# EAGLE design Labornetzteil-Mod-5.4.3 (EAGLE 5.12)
OC_FARNELL: unknown
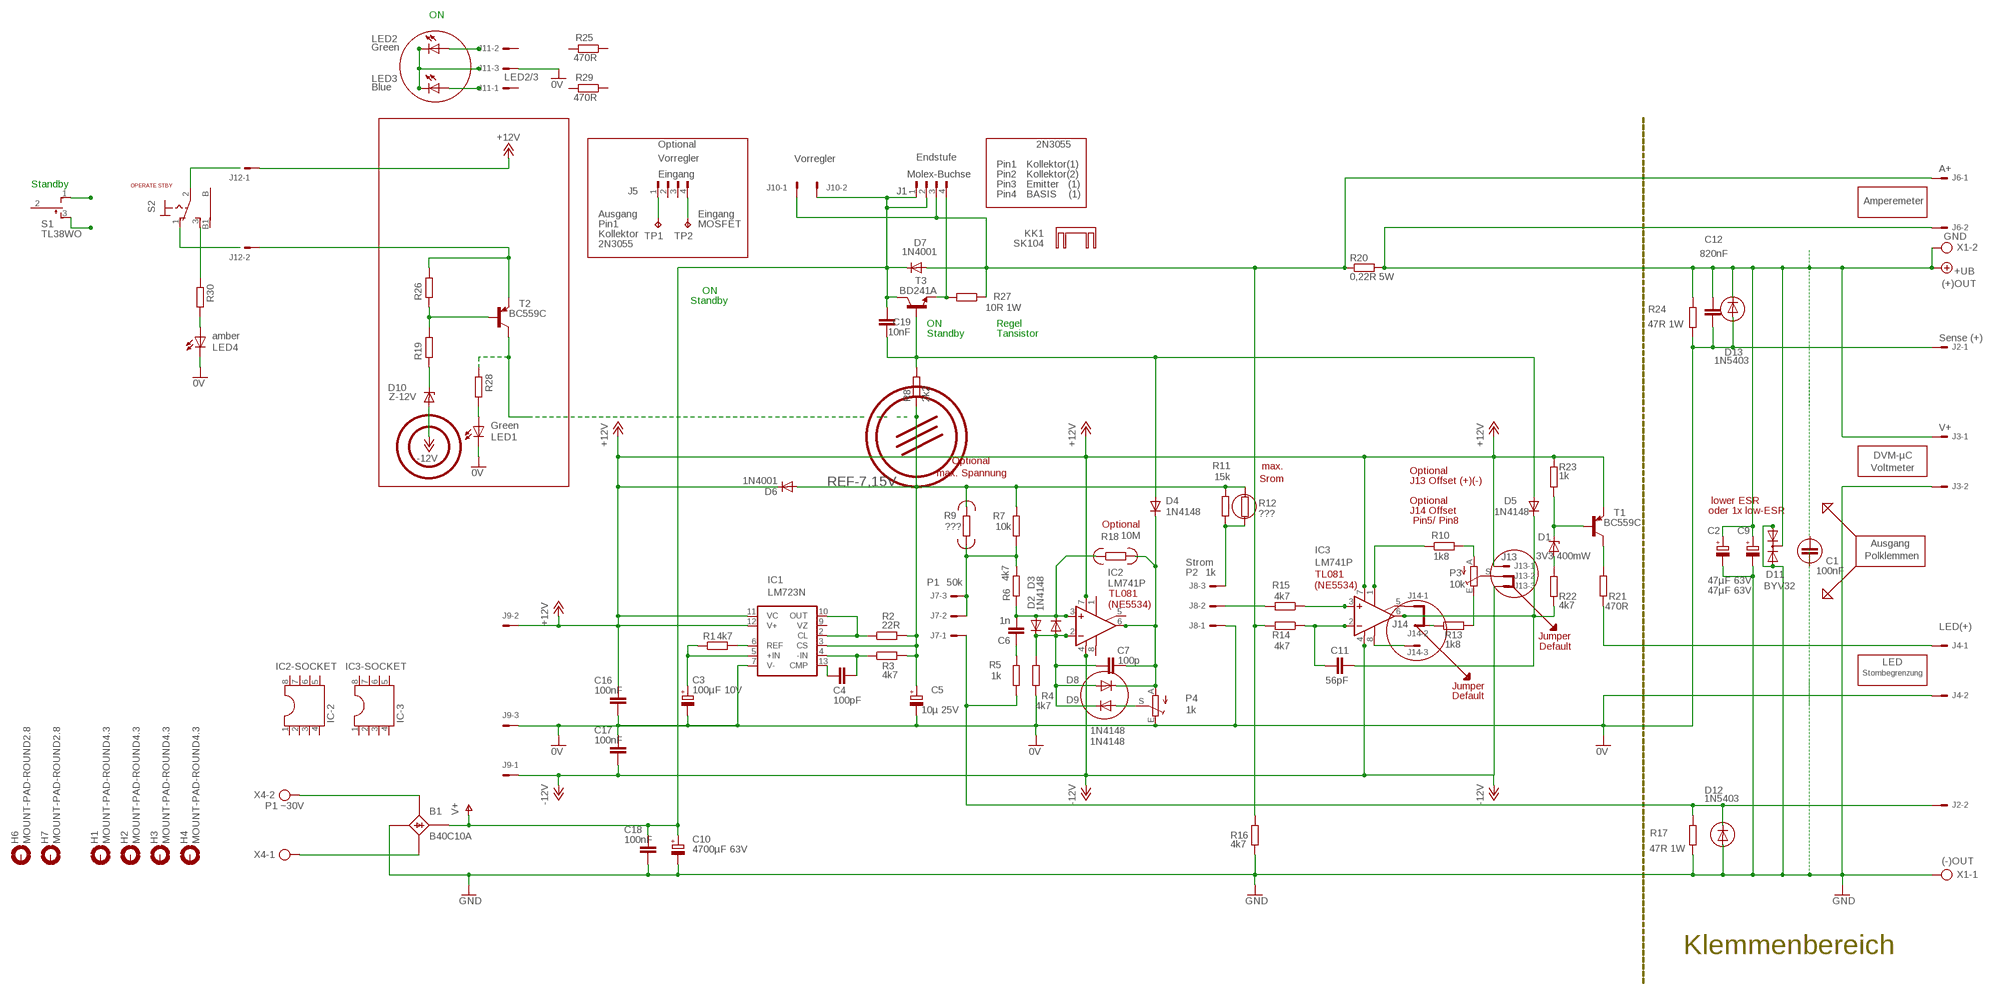
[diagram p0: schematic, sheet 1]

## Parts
B1  B40C10A  B25A-  [B25A-]
C1  100nF  C-EU025-024X044  [C025-024X044]
C2  47µF 63V  CPOL-EUE2.5-6  [E2,5-6]
C3  100µF 10V  CPOL-EUE5-8.5  [E5-8,5]
C4  100pF  C-EU025-024X044  [C025-024X044]
C5  10µ 25V  CPOL-EUE5-8.5  [E5-8,5]
C6  1n  C-EU025-024X044  [C025-024X044]
C7  100p  C-EU025-024X044  [C025-024X044]
C9  47µF 63V  CPOL-EUE2.5-6  [E2,5-6]
C10  4700µF 63V  CPOL-EUE10-35  [EB35D]
C11  56pF  C-EU025-024X044  [C025-024X044]
C12  820nF  C-EU025-024X044  [C025-024X044]
C16  100nF  C-EU025-030X050  [C025-030X050]
C17  100nF  C-EU025-024X044  [C025-024X044]
C18  100nF  C-EUC1206K  [C1206K]
C19  10nF  C-EU025-024X044  [C025-024X044]
D1  3V3 400mW  ZENER-DIODEDO34-7  [DO34Z7]
D2  1N4148  1N4148DO35-10  [DO35-10]
D3  1N4148  1N4148DO35-10  [DO35-10]
D4  1N4148  1N4148DO35-10  [DO35-10]
D5  1N4148  1N4148DO35-10  [DO35-10]
D6  1N4001  1N4004  [DO41-10]
D7  1N4001  1N4004  [DO41-10]
D8  1N4148  DIODE-D-2.5  [D-2.5]
D9  1N4148  DIODE-D-2.5  [D-2.5]
D10  Z-12V  ZENER-DIODEDO34-7  [DO34Z7]
D11  BYV32  [TO220ABS]
D12  1N5403  DIODE-D-5  [D-5]
D13  1N5403  DIODE-D-5  [D-5]
H1  MOUNT-PAD-ROUND4.3  [4,3-PAD]
H2  MOUNT-PAD-ROUND4.3  [4,3-PAD]
H3  MOUNT-PAD-ROUND4.3  [4,3-PAD]
H4  MOUNT-PAD-ROUND4.3  [4,3-PAD]
H6  MOUNT-PAD-ROUND2.8  [2,8-PAD]
H7  MOUNT-PAD-ROUND2.8  [2,8-PAD]
IC1  LM723N  [DIL14]
IC2  LM741P  [DIL08]
IC2-SOCKET  IC-2  DIL8S  [SOCKET-08]
IC3  LM741P  [DIL08]
IC3-SOCKET  IC-3  DIL8S  [SOCKET-08]
J1  Endstufe  FLOPPY-4  [FLOPPY-4]
J2  Sense (+)  22-27-2021-02  [6410-02]
J3  V+  22-27-2021-02  [6410-02]
J4  LED(+)  22-27-2021-02  [6410-02]
J5  Vorregler  FLOPPY-4  [FLOPPY-4]
J6  A+  22-27-2021-02  [6410-02]
J7  Spannung  22-27-2031-03  [6410-03]
J8  Strom  22-27-2031-03  [6410-03]
J9  -12V  22-27-2031-03  [6410-03]
J10  Vorregler  22-27-2021-02  [6410-02]
J11  LED2/3  22-27-2031-03  [6410-03]
J12  Relaise 12V  22-27-2021-02  [6410-02]
J13  J13  22-27-2031-03  [6410-03]
J14  J14  22-27-2031-03  [6410-03]
KK1  SK104  [SK104]
LED1  Green  LED5MM  [LED5MM]
LED2  Green  LED5MM  [LED5MM]
LED3  Blue  LED5MM  [LED5MM]
LED4  amber  LED5MM  [LED5MM]
P3  10k  TRIM_EU-CA6V  [CA6V]
P4  1k  TRIM_EU-S63X  [S63X]
R1  4k7  R-EU_0204/2V  [0204V]
R2  22R  R-EU_0204/2V  [0204V]
R3  4k7  R-EU_0204/2V  [0204V]
R4  4k7  R-EU_0207/10  [0207/10]
R5  1k  R-EU_0207/10  [0207/10]
R6  4k7  R-EU_0207/10  [0207/10]
R7  10k  R-EU_0207/10  [0207/10]
R8  2k2  R-EU_0207/10  [0207/10]
R9  ???  R-EU_0207/10  [0207/10]
R10  1k8  R-EU_0207/10  [0207/10]
R11  15k  R-EU_0207/10  [0207/10]
R12  ???  R-EU_0207/10  [0207/10]
R13  1k8  R-EU_0207/10  [0207/10]
R14  4k7  R-EU_0207/10  [0207/10]
R15  4k7  R-EU_0207/10  [0207/10]
R16  4k7  R-EU_0207/10  [0207/10]
R17  47R 1W  R-EU_0207/10  [0207/10]
R18  10M  R-EU_0204/2V  [0204V]
R19  R-EU_0204/2V  [0204V]
R20  0,22R 5W  R-EU_0617/22  [0617/22]
R21  470R  R-EU_0207/10  [0207/10]
R22  4k7  R-EU_0207/10  [0207/10]
R23  1k  R-EU_0207/10  [0207/10]
R24  47R 1W  R-EU_0207/10  [0207/10]
R25  470R  R-EU_0204/2V  [0204V]
R26  R-EU_0204/2V  [0204V]
R27  10R 1W  R-EU_0613/15  [P0613/15]
R28  R-EU_0204/2V  [0204V]
R29  470R  R-EU_0204/2V  [0204V]
R30  R-EU_0204/2V  [0204V]
S1  TL38WO  [TL3XWO]
S2  316-917  [316-917]
T1  BC559C  -PNP-TO92  [TO92]
T2  BC559C  -PNP-TO92  [TO92]
T3  BD241A  2SC1307  [TO220AV]
TP1  TPPAD1-20Y  [P1-20Y]
TP2  TPPAD1-20Y  [P1-20Y]
X1  GND  AK300/2  [AK300/2]
X4  P1 ~30V  AK300/2  [AK300/2]

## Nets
0V: C3.- C5.- C12.2 C16.1 C17.2 D13.A IC1.7(V-) J2.1 J4.2 J8.1 J9.3 J11.3 LED1.K(C) LED4.K(C) P4.E R4.1 R24.2
+12V: C16.2 D6.C IC1.11(VC) IC1.12(V+) IC2.7(V+) IC3.7(V+) J9.2 J12.1 J13.1 R23.1 T1.1(E)
+UB: C2.+ C9.+ C12.1 D11.C D13.C J3.1 J6.2 R20.2 R24.1 X1.2
-12V: C17.1 D10.A IC2.4(V-) IC3.4(V-) J9.1 J13.3
-SENSE: D12.C J2.2 J7.1 R5.1 R17.1
GND: B1.-1(-) C2.- C9.- C10.- C18.1 D11.A1 D11.A2 D12.A J3.2 R16.2 R17.2 X1.1
N$1: C3.+ IC1.5(+IN) R1.1
N$3: B1.AC1-(AC1) X4.2
N$4: B1.AC2-(AC2) X4.1
N$5: IC1.6(REF) R1.2
N$7: C6.1 R5.2
N$8: J7.2 J7.3 R6.2 R7.1 R9.1
N$9: IC1.2(CL) IC1.10(OUT) R2.1
N$10: C4.2 IC1.4(-IN) R3.1
N$11: J5.1 TP1.TP
N$12: C4.1 IC1.13(CMP)
N$13: J4.1 R21.1
N$14: S2.2(P)
N$15: LED1.A R28.1
N$16: C7.1 D2.C D3.A D8.A D9.C IC2.2(-IN) R4.2
N$17: C19.1 D4.A D5.A R8.2 T3.1(B)
N$18: C7.2 D4.C D8.C IC2.6(OUT) P4.A R18.2
N$19: J8.3 R11.1 R12.2
N$21: R21.2 T1.3(C)
N$22: C6.2 D2.A D3.C IC2.3(+IN) R6.1 R18.1
N$23: D1.C R23.2 T1.2(B)
N$24: J8.2 R15.2
N$25: D1.A R22.1
N$26: J5.4 TP2.TP
N$27: D7.A J1.3 J6.1 J10.1 R14.2 R16.1 R20.1 R27.1
N$29: C11.1 IC3.2(-IN) R14.1
N$30: IC3.5(ON2) J14.1
N$31: J12.2 R26.1 T2.1(E)
N$32: D10.C R19.2
N$33: IC3.3(+IN) R15.1
N$34: C11.2 D5.C IC3.6(OUT) R22.2
N$35: R19.1 R26.2 T2.2(B)
N$36: IC3.1(ON1) R10.1
N$37: S2.1(O)
N$40: LED2.K(C) LED3.K(C)
N$41: LED2.A
N$42: J1.4 R27.2 T3.3(E)
N$43: P3.E R13.2
N$44: P3.A R10.2
N$45: LED3.A
N$46: D9.A P4.S
N$48: S1.1(O)
N$49: S1.3(S)
N$50: J13.2 P3.S
N$51: J14.2 R13.1
N$52: IC3.8(OPT) J14.3
N$54: LED4.A R30.1
N$55: R30.2 S2.3(S)
REF-7,15V: C5.+ D6.A IC1.3(CS) R2.2 R3.2 R7.2 R8.1 R9.2 R11.2 R12.1 R28.2 T2.3(C)
V+: B1.+1(+) C10.+ C18.2 C19.2 D7.C J1.1 J1.2 J10.2 T3.2(C)
Unconnected: B1.+ B1.- B1.AC1 B1.AC2 C1.1 C1.2 H1.B4,3(MOUNT) H2.B4,3(MOUNT) H3.B4,3(MOUNT) H4.B4,3(MOUNT) H6.B2,8(MOUNT) H7.B2,8(MOUNT) IC1.9(VZ) IC2-SOCKET.1 IC2-SOCKET.2 IC2-SOCKET.3 IC2-SOCKET.4 IC2-SOCKET.5 IC2-SOCKET.6 IC2-SOCKET.7 IC2-SOCKET.8 IC2.1(ON1) IC2.5(ON2) IC2.8(OPT) IC3-SOCKET.1 IC3-SOCKET.2 IC3-SOCKET.3 IC3-SOCKET.4 IC3-SOCKET.5 IC3-SOCKET.6 IC3-SOCKET.7 IC3-SOCKET.8 J5.2 J5.3 J11.1 J11.2 R25.1 R25.2 R29.1 R29.2 S1.2(P) S2.B S2.B1

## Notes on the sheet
- ON
- Optional | 2N3055
- Pin1 | Kollektor(1)
- Eingang | Molex-Buchse | Pin2 | Kollektor(2)
- Standby | OPERATE STBY | Pin3 | Emitter   (1)
- Pin4 | BASIS    (1)
- Amperemeter
- Ausgang | Eingang
- Pin1 | MOSFET
- Kollektor
- 2N3055
- ON | (+)OUT
- Standby
- ON | Regel
- Standby | Tansistor
- ---------------------------------------------
- DVM-µC
- Optional
- max. | Voltmeter
- max. Spannung | Optional
- Srom | J13 Offset (+)(-)
- Optional | lower ESR
- J14 Offset | oder 1x low-ESR
- Pin5/ Pin8
- Optional
- ---------------------------------------------
- Ausgang
- Polklemmen
- Strom
- P2 | 1k | TL081
- P1 | 50k
- (NE5534)
- TL081
- (NE5534)
- Jumper
- Default
- LED
- Stombegrenzung
- Jumper
- Default
- ---------------------------------------------
- (-)OUT
- --------------------------------------------------------
- Klemmenbereich

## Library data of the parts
B1 = rectifier:B25A-: RECTIFIER 25-A bridge
C1 C4 C6 C7 C11 C12 C16-C19 = rcl:C-EU: CAPACITOR, European symbol
C2 C3 C5 C9 C10 = rcl:CPOL-EU: POLARIZED CAPACITOR, European symbol
D1 D10 = diode:ZENER-DIODE: Z-Diode
D2-D5 = diode:1N4148: DIODE
D6 D7 = diode:1N4004: DIODE
D8 D9 D12 D13 = diode:DIODE-: DIODE
D11 = diode:BYV32: DIODE 2 x Si diode 200 V, 20 A/230 Apeak, 25 ns
H1-H4 H6 H7 = holes:MOUNT-PAD-ROUND: MOUNTING PAD, round
IC1 = linear:*723: Positive VOLTAGE REGULATOR
IC2 IC3 = linear:*741: OP AMP
IC2-SOCKET IC3-SOCKET = ic-package:DIL8: Dual In Line / Socket
J1 J5 = con-amp:FLOPPY-4: MATE N-LOCK Floppy / HDD conector Distributor: Bürklin 71F970; OC_FARNELL: unknown; OC_NEWARK: unknown
J2-J4 J6 J10 J12 = con-molex:22-?-02: CONNECTOR; OC_FARNELL: unknown; OC_NEWARK: unknown
J7-J9 J11 J13 J14 = con-molex:22-?-03: CONNECTOR wire to board 2.54 mm (.1 inch) pitch header; OC_FARNELL: unknown; OC_NEWARK: unknown
KK1 = heatsink:SK104: HEATSINK
LED1-LED4 = led:LED: LED
P3 P4 = pot:TRIM_EU-: POTENTIOMETER
R1-R30 = rcl:R-EU_: RESISTOR, European symbol
S1 = switch:TL38WO: TINY SWITCH ON OFF MOM Source: http://www2.produktinfo.conrad.com/datenblaetter/700000-724999/705152-da-01-de-Subminiaturschalter_TL_36WO.pdf
S2 = switch:316-917: TOGGLE SWITCH Mors, distributor RS Components
T1 T2 = transistor:*-PNP-: PNP Transistror
T3 = transistor:2SC1307: NPN Transistor Silicon Epitaxial, High Frequency Power Amplifier Source: 2SC1307.pdf
TP1 TP2 = testpad:TP: Test pad
X1 X4 = con-ptr500:AK300/2: CONNECTOR; OC_FARNELL: unknown; OC_NEWARK: unknown

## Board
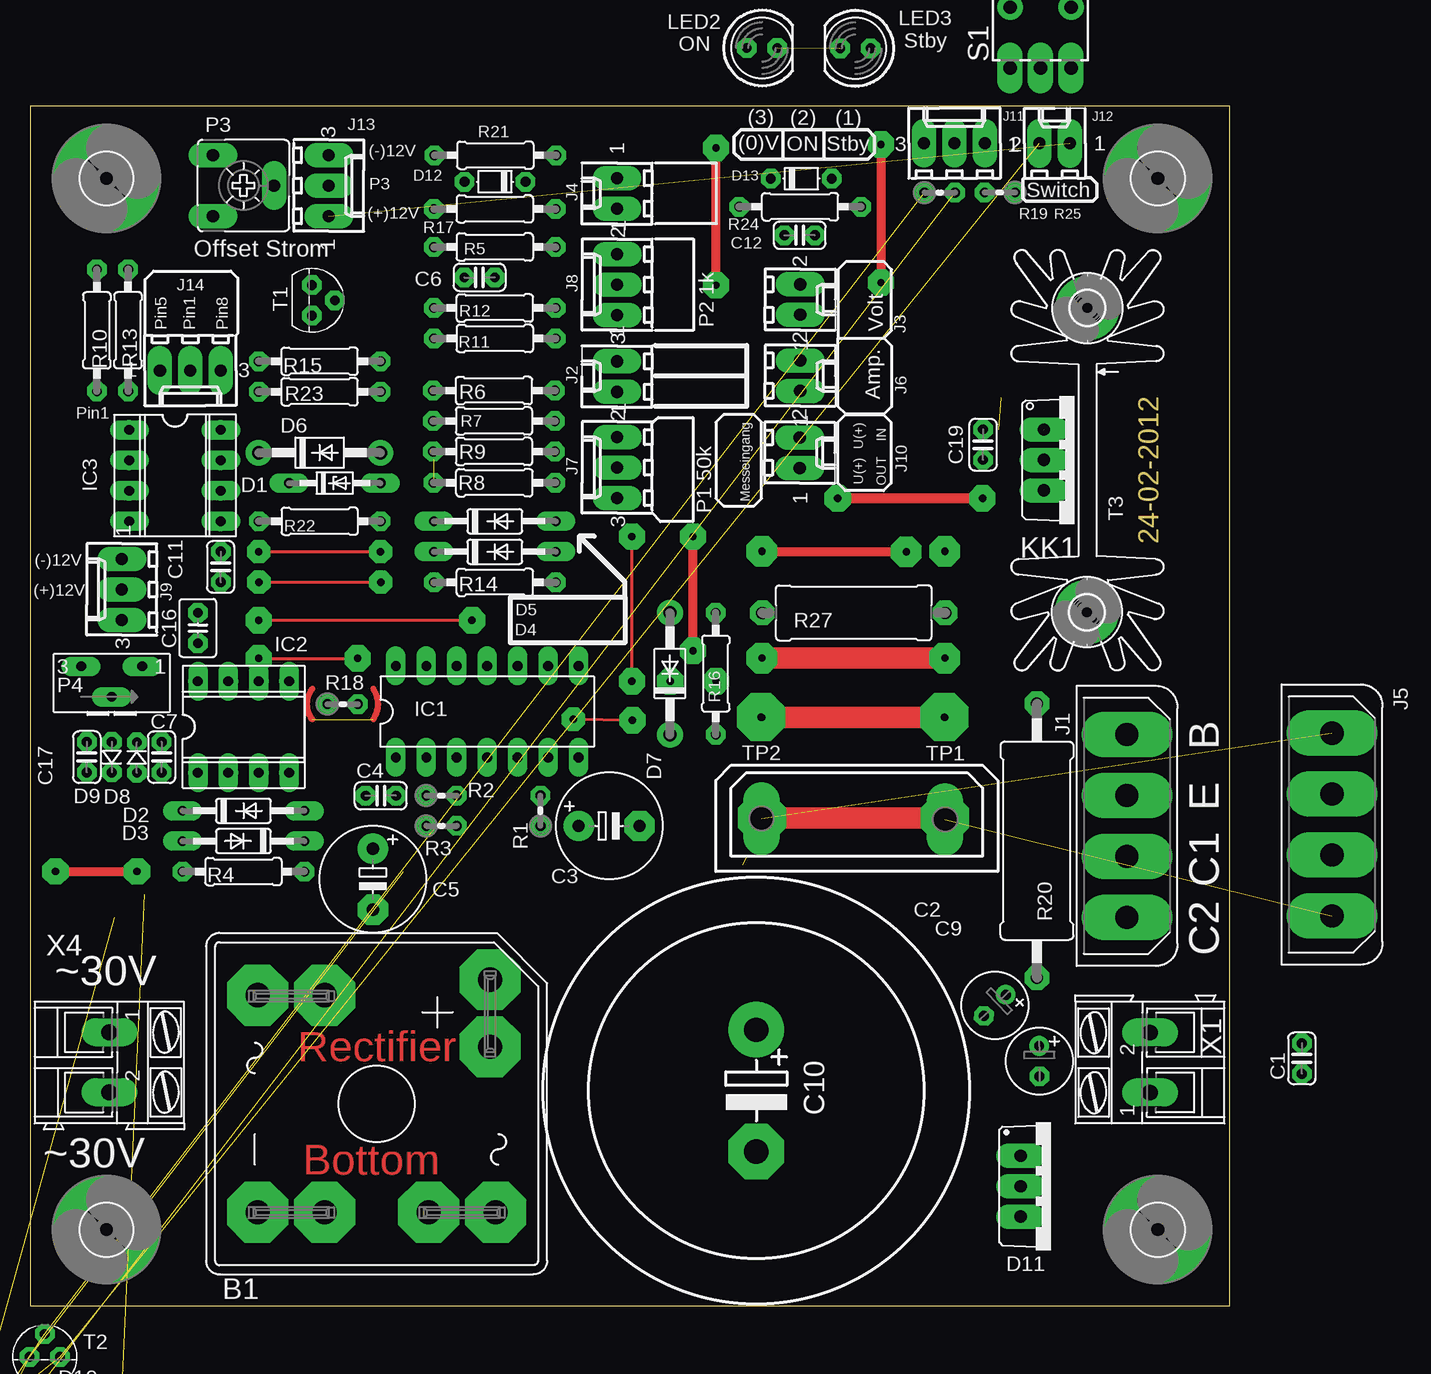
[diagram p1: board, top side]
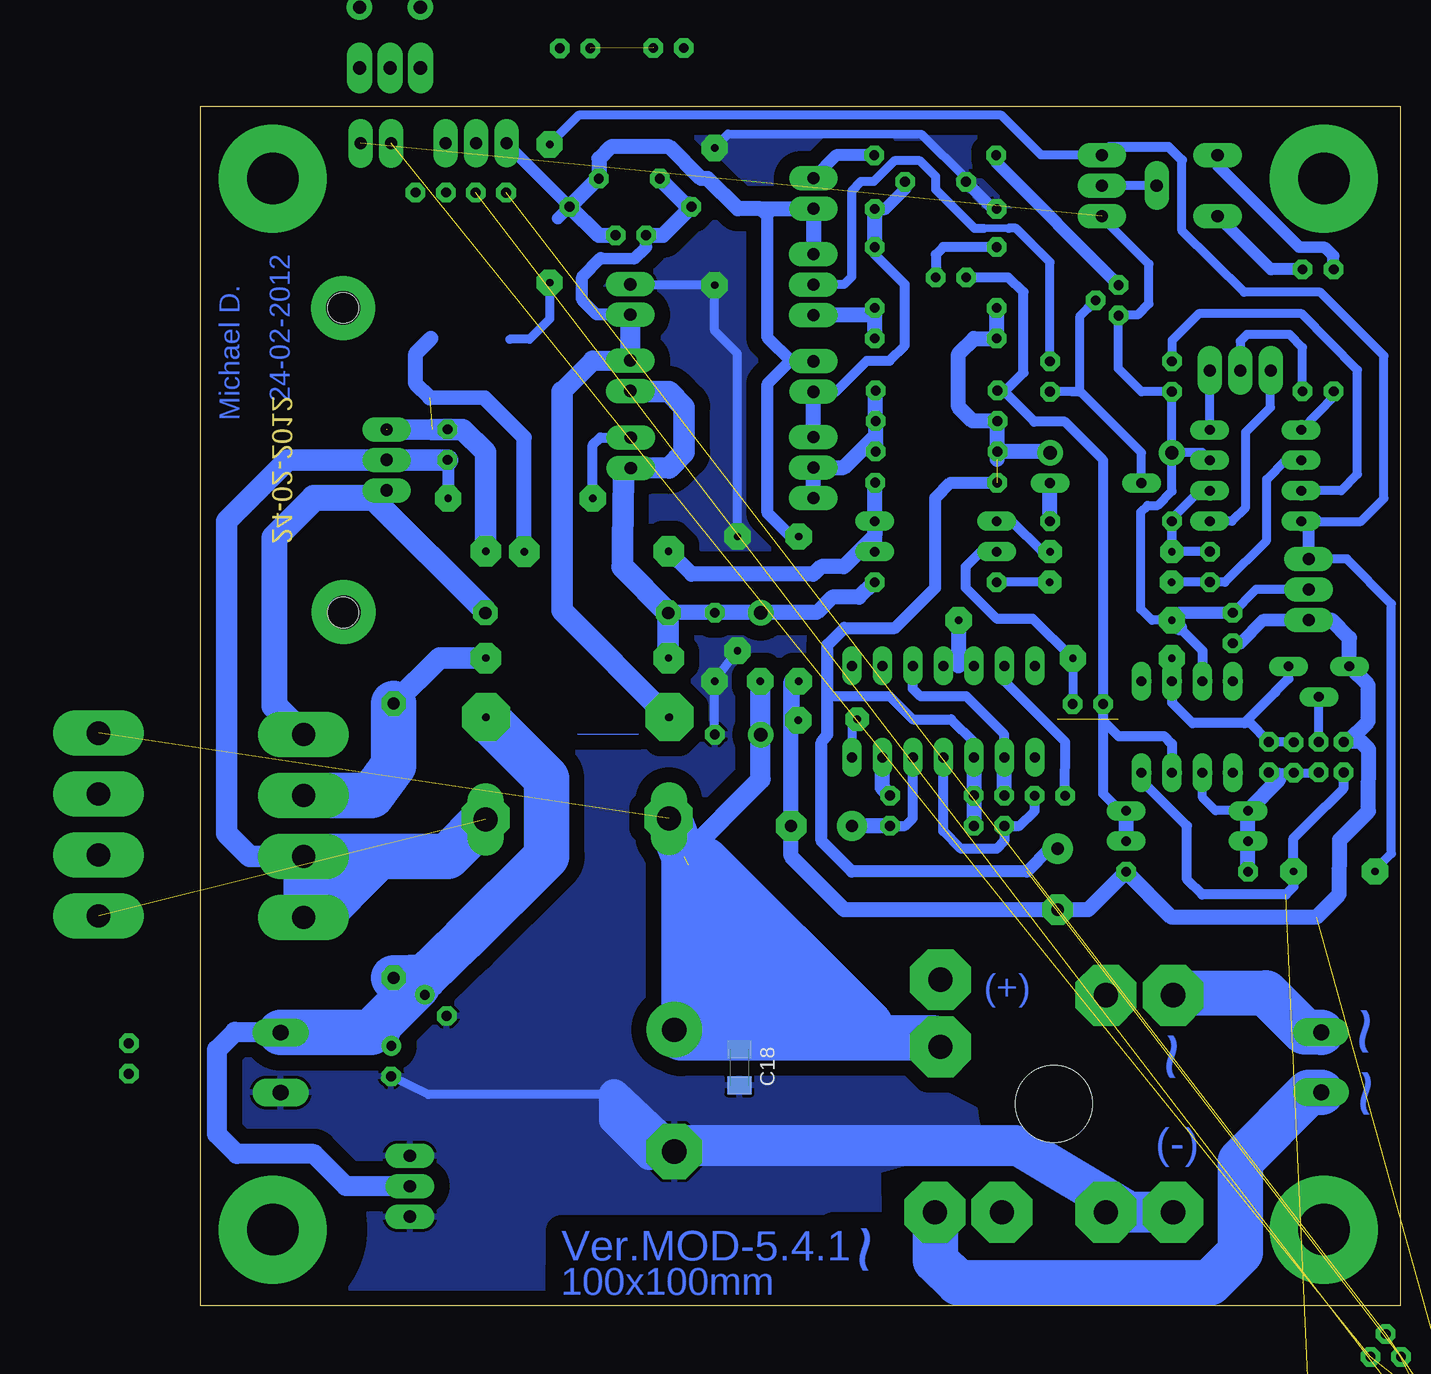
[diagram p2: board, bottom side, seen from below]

Size 100 x 100 mm. Coordinates in mm from the lower left corner, seen from the top.
Outline: 0,0 100,0 100,100 0,100 0,0
Copper layers (1*16): Top 0.035mm / dielectric 1.5mm / Bottom 0.035mm
Design rules "default *": minimum track width 30mil, minimum drill 24mil, track to track 8mil, track to pad 8mil, pad to pad 8mil, via to via 8mil, smd to smd 8mil, copper to edge 0.5mm, drill to drill 8mil, minimum pad ring 10mil, minimum via ring 8mil, stop-mask expansion 4mil, vias tented up to drill 0mil, thermal gap 10mil

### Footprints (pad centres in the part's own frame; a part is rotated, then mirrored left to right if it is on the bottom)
B25A- = drill 2.007 pad 5.08 octagon: + -10.338,9.449; +1 -4.75,9.449; - 9.042,-4.343; -1 9.042,-9.931; AC1 9.042,4.343; AC1- 9.042,9.931; AC2 -9.042,-4.343; AC2- -9.042,-9.931 | hole 6.401: 0,0
C025-024X044 = drill 0.813 octagon: 1 -1.27,0; 2 1.27,0
E2,5-6 = drill 0.813 pad 1.6 round: + -1.27,0 | drill 0.813 pad 1.6 octagon: - 1.27,0
E5-8,5 = drill 1.016 pad 2.54 round: + -2.54,0 | drill 1.016 pad 2.54 octagon: - 2.54,0
EB35D = drill 2.007 pad 4.597 round: + -5.08,0 | drill 2.007 pad 4.597 octagon: - 5.08,0
C025-030X050 = drill 0.813 octagon: 1 -1.27,0; 2 1.27,0
C1206K = smd 1.5 x 2: 1 -1.5,0; 2 1.5,0
DO34Z7 = drill 0.813 long: A 3.81,0; C -3.81,0
DO35-10 = drill 0.813 long: A 5.08,0; C -5.08,0
DO41-10 = drill 1.118 round: A 5.08,0; C -5.08,0
D-2.5 = drill 0.813 octagon: A 1.27,0; C -1.27,0
TO220ABS = drill 1.016 long: A1 -2.54,-2.54; A2 2.54,-2.54; C 0,-2.54
D-5 = drill 0.813 octagon: A 2.54,0; C -2.54,0
4,3-PAD = drill 4.3 pad 9 round: B4,3 0,0
2,8-PAD = drill 2.8 pad 5.334 round: B2,8 0,0
DIL14 = drill 0.813 long: 1 -7.62,-3.81; 2 -5.08,-3.81; 3 -2.54,-3.81; 4 0,-3.81; 5 2.54,-3.81; 6 5.08,-3.81; 7 7.62,-3.81; 8 7.62,3.81; 9 5.08,3.81; 10 2.54,3.81; 11 0,3.81; 12 -2.54,3.81; 13 -5.08,3.81; 14 -7.62,3.81
DIL08 = drill 0.813 pad 1.27 round: 1 -3.81,-3.81; 2 -1.27,-3.81; 3 1.27,-3.81; 4 3.81,-3.81; 5 3.81,3.81; 6 1.27,3.81; 7 -1.27,3.81; 8 -3.81,3.81
SOCKET-08 = drill 0.813 long: 1 -3.81,-3.81; 2 -1.27,-3.81; 3 1.27,-3.81; 4 3.81,-3.81; 5 3.81,3.81; 6 1.27,3.81; 7 -1.27,3.81; 8 -3.81,3.81
FLOPPY-4 = drill 1.93 pad 3.81 long: 1 7.62,0; 2 2.54,0; 3 -2.54,0; 4 -7.62,0
6410-02 = drill 1.016 long: 1 1.27,0; 2 -1.27,0
6410-03 = drill 1.016 long: 1 2.54,0; 2 0,0; 3 -2.54,0
SK104 = hole 2.54: -12.7,-0.762; 12.7,-0.762
LED5MM = drill 0.813 octagon: A -1.27,0; K 1.27,0
CA6V = drill 1.016 long: A -2.54,-2.54; E 2.54,-2.54; S 0,2.54
S63X = drill 0.813 long: A 2.54,0; E -2.54,0; S 0,-2.54
0204V = drill 0.813 octagon: 1 -1.27,0; 2 1.27,0
0207/10 = drill 0.813 octagon: 1 -5.08,0; 2 5.08,0
0617/22 = drill 1.016 octagon: 1 -11.43,0; 2 11.43,0
P0613/15 = drill 1.016 octagon: 1 -7.62,0; 2 7.62,0
TL3XWO = drill 1.1 pad 1.422 long: 1 -2.54,-5.08; 2 0,-5.08; 3 2.54,-5.08 | drill 1.1 pad 1.676 round: M1 -2.54,0; M2 2.54,0
316-917 = drill 1.016 octagon: 1 10.16,2.54; 2 15.24,0; 3 10.16,-2.54 | drill 1.016 pad 2.54 round: B 0,-5.08; B1 0,5.08
TO92 = drill 0.813 octagon: 1 1.27,0; 2 0,1.905; 3 -1.27,0
TO220AV = drill 1.016 long: 1 -2.54,-2.54; 2 0,-2.54; 3 2.54,-2.54
P1-20Y = drill 2.007 pad 2.54 long: TP 0,0
AK300/2 = drill 1.321 long: 1 -2.515,0; 2 2.489,0

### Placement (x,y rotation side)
B1  28.86,16.85 270 top
C1  not placed on the board
C2  80.4,25.05 224 top
C3  48.24,40.01 0 top
C4  29.21,42.53 0 top
C5  28.55,35.56 270 top
C6  37.45,85.72 180 top
C7  10.95,45.74 90 top
C9  84.11,20.4 270.5 top
C10  60.51,17.94 270 top
C11  15.87,61.6 90 top
C12  64.13,89.25 0 top
C16  13.96,56.51 90 top
C17  4.7,45.74 90 top
C18  55.09,19.88 90 bottom
C19  79.41,71.79 270 top
D1  25.38,68.58 0 top
D2  17.76,41.27 0 top
D3  17.76,38.73 180 top
D4  38.72,62.87 0 top
D5  38.72,65.41 0 top
D6  24.11,71.12 0 top
D7  53.32,52.7 90 top
D8  8.88,45.71 270 top
D9  6.79,45.74 90 top
D10  not placed on the board
D11  85.09,9.97 270 top
D12  38.73,93.71 180 top
D13  64.26,93.97 0 top
H1  6.35,93.98 0 top
H2  6.35,6.35 0 top
H3  93.98,93.98 0 top
H4  93.98,6.35 0 top
H6  88.12,83.19 0 top
H7  88.07,57.82 0 top
IC1  38.08,49.53 0 top
IC2  17.76,48.26 0 top
IC2-SOCKET  17.78,48.26 0 top
IC3  12.05,69.22 270 top
IC3-SOCKET  12.06,69.22 270 top
J1  91.42,40.01 270 top
J2  48.91,77.47 90 top
J3  64.17,83.89 270 top
J4  48.91,92.73 90 top
J5  not placed on the board
J6  64.17,77.55 270 top
J7  48.92,69.88 90 top
J8  48.92,85.13 90 top
J9  7.62,59.72 90 top
J10  64.14,71.12 270 top
J11  77.04,96.92 0 top
J12  85.39,96.91 0 top
J13  24.87,93.39 270 top
J14  13.34,77.97 180 top
KK1  88.88,70.49 270 top
LED1  not placed on the board
LED2  not placed on the board
LED3  not placed on the board
LED4  not placed on the board
P3  17.76,93.39 270 top
P4  6.78,53.32 0 top
R1  42.53,41.27 90 top
R2  34.27,42.55 0 top
R3  34.27,40.01 0 top
R4  17.76,36.2 180 top
R5  38.72,88.27 180 top
R6  38.65,76.3 0 top
R7  38.65,73.76 180 top
R8  38.68,68.62 0 top
R9  38.65,71.22 180 top
R10  5.54,81.32 90 top
R11  38.72,80.64 180 top
R12  38.72,83.19 0 top
R13  8.15,81.32 90 top
R14  38.72,60.31 0 top
R15  24.11,78.74 0 top
R16  57.13,52.7 270 top
R17  38.72,91.44 180 top
R18  26.04,50.16 0 top
R19  75.81,92.81 0 top
R20  83.91,38.78 270 top
R21  38.76,95.92 180 top
R22  24.11,65.41 180 top
R23  24.11,76.2 0 top
R24  64.17,91.62 0 top
R25  80.81,92.81 180 top
R26  not placed on the board
R27  68.64,57.77 0 top
R28  not placed on the board
R29  not placed on the board
R30  not placed on the board
S1  not placed on the board
S2  not placed on the board
T1  23.48,83.82 270 top
T2  1.2,-4.25 0 top
T3  87.04,70.52 270 top
TP1  76.26,40.55 0 top
TP2  60.95,40.62 0 top
X1  93.33,20.29 90 top
X4  6.59,20.29 270 top

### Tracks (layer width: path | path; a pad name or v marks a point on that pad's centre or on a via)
0V  (via drill 0.61 pad 1.93, 0.61 pad 2.18)  (2 unrouted)
  Top 0.254: v50.15,52.07 v50.15,64.14 | v50.19,48.81 v45.27,48.9
  Bottom 0.254: v50.19,48.81 50.19,50.12 v50.15,52.07
  Bottom 0.762: IC1.7 45.7,48.51 v45.27,48.9 | 74.5,96.74 J11.3
  Bottom 1.016: 50.78,52.08 v50.15,52.07 | 48.92,91.48 48.88,91.48 J4.2 | 53.34,91.46 52.73,90.85 52.73,80.68 50.79,78.74 J2.1 50.86,78.74 52.73,76.87 52.73,66.07 50.19,63.53 50.19,63.54 v50.15,64.14 | 11.46,57.16 J9.3 | 11.46,57.16 13.31,55.25 C16.1 | 5.72,57.16 11.46,57.16 | 70.23,90.64 R24.2 74.36,96.74 74.5,96.74
  Bottom 1.27: 50.78,52.08 C3.- 50.78,37.47 46.34,33.02 C5.- 26.02,33.02 R4.1 22.84,36.18 19.06,32.4 6.99,32.4 5.08,34.31 5.04,38.85 2.65,41.22 2.63,46.4 3.27,47.03 4.42,47.03 C17.2 4.4,46.99 2.66,48.73 2.66,51.74 P4.E 4.24,55.68 5.72,57.16 | J4.2 53.34,91.46 55.21,91.46 57.73,93.98 58.28,93.98 60.91,96.61 65.83,96.61 66.8,95.64 D13.A 66.9,93.97 R24.2 66.81,89.25 C12.2 | 48.92,91.48 J8.1
+12V  (via drill 0.61 pad 2.18)  (1 unrouted)
  Top 0.254: v19.03,57.15 v36.81,57.15
  Bottom 0.762: T1.1 23.51,82.52 23.51,78.14 21.57,76.2 R23.1 D6.C | IC3.7 15.86,70.49 16.52,71.15 19,71.15 D6.C | C16.2 12.02,59.72 J9.2 | 17.75,55.87 v19.03,57.15 20.69,57.15 21.62,58.08 21.62,66.16 21.05,66.73 20.22,66.73 19.03,67.92 D6.C | T1.1 | J13.1 24.87,90.77 20.95,86.85 20.95,83.53 21.83,82.65 23.38,82.65 T1.1
  Bottom 0.813: IC1.12 36.85,53.34 IC1.11 | IC2.7 16.49,54.61 v19.03,57.15
  Bottom 1.016: C16.2 18.41,57.77 v19.03,57.15
  Bottom 1.27: v19.03,57.15 18.4,56.52 | v36.81,57.15 36.81,53.38 36.85,53.34
+UB  (via drill 0.61 pad 2.18)
  Top 1.778: v76.24,49.04 v60.99,49.04
  Bottom 0.762: R20.2 82.52,25.95 C9.+ 84.43,22.01 84.43,22.66 81.31,25.78 C2.+
  Bottom 1.016: J3.1 66.99,82.65 68.19,83.85 68.19,85.75 66.64,87.34 63.85,87.31 62.87,88.27 62.87,88.92 C12.1
  Bottom 1.27: J3.1 64.1,82.54 | C12.1 61.44,89.25 R24.1 59.31,91.85 59.62,91.85 61.72,93.95 D13.C
  Bottom 1.676: J3.1 J6.2 67.3,78.81 69.88,76.23 | D11.C 87.87,9.97 90.56,12.66 96.98,12.66 98.63,14.3 98.63,21.36 97.13,22.85 93.4,22.85 X1.2
  Bottom 1.778: 69.88,76.23 69.88,57.95 v60.99,49.04
  Bottom 3.81: v76.24,49.04 71.18,43.96 71.15,37.48 78.06,30.58 81.32,27.4 R20.2 83.24,26.67 81.92,26.67 85.8,22.78 X1.2
-12V  (via drill 0.61 pad 2.18)  (1 unrouted)
  Top 0.762: v2.09,36.21 v8.89,36.21 | v70.9,96.82 v70.9,85.3
  Bottom 0.762: J9.1 4.45,62.26 0.73,58.52 0.74,37.7 2.09,36.34 v2.09,36.21 | v70.9,96.82 68.51,99.25 33.24,99.25 29.91,95.93 J13.3 | v70.9,85.3 70.9,82.27 72.59,80.57 74.22,80.57 | 18.2,95.51 18.2,89.62 13.01,84.48 6.65,84.48 1.36,79.19 1.36,67.31 3.28,65.39 8.22,65.39 IC3.4
  Bottom 0.813: IC3.4 8.21,65.44 | C17.1 4.72,43.15 7.63,40.24 7.62,40.25 8.89,38.98 v8.89,36.22 v8.89,36.21 8.89,34.92 9.53,34.29 16.51,34.29 17.78,35.56 17.78,40.01 21.57,43.8 IC2.4 | 18.2,95.51 19.29,96.59 24.2,96.59 J13.3
  Bottom 1.016: IC2.4 21.57,43.42 | IC3.4 8.23,65.41 7.62,64.8 J9.1 | 8.21,65.44 6.99,65.44
-SENSE
  Bottom 0.762: 43.8,87.63 R5.1 | J2.2 48.87,76.24
  Bottom 0.813: 43.8,87.63 41.29,85.13 41.29,80.05 42.56,78.78 44.47,78.78 47.01,76.24 48.87,76.24
  Bottom 1.016: 43.55,91.36 R17.1 42.94,91.43 41.27,93.1 D12.C
  Bottom 1.27: R5.1 R17.1 | J2.2 48.91,72.43 J7.1
GND  (via drill 0.61 pad 2.18)
  Top 0.762: v57.15,85.09 v57.15,96.52 | v55.24,54.61 v55.24,64.14
  Bottom 0.762: R16.2 57.15,47.64 v57.15,52.07 v55.24,54.61 | 65.54,17.62 81.02,17.62 C9.- | 33.88,91.44 R17.2 | J3.2 64.11,85.09 v57.15,85.09 57.15,81.28 55.24,79.38 v55.24,64.14 | v57.15,96.52 56.01,97.7 39.92,97.66 36.16,93.94 36.2,93.91 D12.A
  Bottom 1.016: 33.88,91.44 33.92,91.44 D12.A
  Bottom 2.54: 62.58,12.58 65.54,15.54 65.54,17.62 C10.-
  Bottom 3.4: B1.-1 22.58,7.81 31.84,13.33 59.4,13.33 C10.-
  pour Bottom (isolate 1.27): -1.27,100.97 -1.27,88.9 31.75,88.9 31.98,37.47 31.98,37.32 31.76,31.84 39.38,31.8 44.01,26.61 43.91,24.84 43.81,20.76 31.96,14.6 43.55,11.23 43.42,-1.01 101.23,-0.92 101.71,101.24
N$1
  Bottom 0.813: IC1.5 40.62,40.64 41.26,40.01 R1.1
  Bottom 1.27: R1.1 C3.+
N$2  (1 unrouted)
  Top 0.508: 23.5,48.9 arc-74 23.5,51.44 | 28.57,48.9 arc74 28.57,51.44
N$3
  Bottom 3.81: X4.2 7.6,17.8 13.34,12.06 13.34,4.45 15.88,1.91 36.83,1.91 38.73,3.81 38.73,7.75 B1.AC1-
N$4
  Bottom 3.81: X4.1 7.95,22.85 11.18,26.08 18.79,26.04 B1.AC2-
N$5
  Bottom 1.27: R1.2 43.16,43.18 IC1.6
N$6  (via drill 0.61 pad 4)
  other vias: 60.91,49.08
N$7
  Bottom 0.813: C6.1 38.72,87.63 38.08,88.27 R5.2
N$8
  Bottom 0.762: 43.8,72.46 43.8,73.66
  Bottom 1.27: R7.1 43.73,73.73 43.8,73.66 | R7.1 R9.1 | R7.1 R6.2 | 43.8,72.46 46.38,69.88 J7.2 J7.3
N$9
  Bottom 0.813: IC1.10 40.62,51.44 39.99,50.8 36.18,50.8 33,47.62 IC1.2
  Bottom 1.27: R2.1 IC1.2
N$10
  Bottom 0.813: C4.2 30.46,41.27 31.73,40.01 R3.1 33,38.73 33.64,38.1 36.6,38.1 38.08,39.58 IC1.4
N$11  (1 unrouted)
N$12
  Bottom 0.813: C4.1 27.92,46.99 33,52.07 IC1.13
N$13
  Bottom 1.016: R21.1 47.02,95.92 J4.1
N$15  (1 unrouted)
N$16
  Bottom 0.762: C7.1 9.71,44.46 | C7.1 9.54,44.47 D8.A 6.82,44.44 D9.C | 10.13,44.23 10.15,44.41 C7.1 | IC2.2 16.49,42.39 15.39,41.29 12.7,41.29 D2.C
  Bottom 1.27: D2.C D3.A R4.2 | D2.C | D2.C 10.12,43.87 10.13,44.23 | C7.1 11,44.22
N$17  (via drill 0.61 pad 2.54)  (2 unrouted)
  Top 0.762: v60.99,62.9 73,62.9 v73.03,62.87
  Bottom 0.762: R8.2 43.76,67.98 | 83.89,73.03 84.47,73.03
  Bottom 1.27: D4.A D5.A | D5.A 43.8,68.59 R8.2 | D5.A 43.8,64.2 46.38,61.62 48.28,61.62 48.92,60.99 59.08,60.99 v60.99,62.9 | v73.03,62.87 73.03,72.39 76.31,75.67 80.92,75.7 82.06,76.85 82.06,79.39 80.81,80.64
  Bottom 1.676: 83.89,73.03 C19.1 83.86,73.06 80.68,73.06
  Bottom 1.778: 80.68,73.06 78.14,73.06 76.24,71.15 v76.24,62.9
N$18  (via drill 0.61 pad 2.18)
  Top 0.254: v19.03,53.98 v27.29,53.98
  Bottom 0.61: 18.99,50.93 IC2.6
  Bottom 0.762: 34.97,62.87 D4.C | v27.29,53.98 27.29,50.18 R18.2 | C7.2 8.91,47.01 D8.C
  Bottom 0.813: IC2.6 v19.03,53.98 | 12.98,48.58 12.5,48.58 C7.2 | 12.98,48.58 17.32,48.58 19,50.26 18.99,50.93 | 34.97,62.87 36.21,61.62 36.21,59.85 33.61,57.26 30.64,57.26 v27.29,53.98 | P4.A 9.32,52.29 10.39,51.22 10.39,51.17 12.98,48.58
N$19
  Bottom 1.27: R11.1 43.8,82.59 | 43.8,82.59 R12.2 | J8.3 43.8,82.59
N$20
  Bottom 3.81: 91.48,32.4 90.21,32.4 85.77,36.85
N$21
  Bottom 0.762: 23.51,85.13 23.51,85.12 T1.3
  Bottom 1: 23.51,85.13 33.64,95.28
  Bottom 1.016: 33.64,95.28 R21.2
N$22
  Bottom 0.61: R6.1 32.9,76.3
  Bottom 0.762: 32.83,76.03 32.83,76.2 | 24.75,49.53 24.77,49.55 | 24.75,50.16 R18.1
  Bottom 0.813: 33.74,76.3 R6.1 32.83,76.2 33,76.2 | IC2.3 19.03,46.86 19.67,47.49 23.48,47.49 24.75,48.76 | C6.2 32.68,85.72 31.41,84.51 31.41,77.79 32.9,76.3 | 22.84,40.77 24.75,42.67 24.75,48.76 | 24.75,48.76 24.75,49.53 24.75,50.16 24.75,70.49 27.95,73.69 30.49,73.69 32.83,76.03
  Bottom 1.27: D3.C 22.84,40.77 D2.A
N$23
  Bottom 0.762: 27.35,76.2 R23.2 | 26.68,76.24 27.35,76.2 | 26.68,76.24 26.68,82.52 26.02,83.19 | D1.C 21.57,71.12 26.68,76.24 | 26.68,76.24 26.68,76.17 27.35,76.2
  Bottom 0.813: T1.2 26.02,83.19
N$24
  Bottom 0.61: 32.66,89.83 34.73,89.83
  Bottom 0.762: J8.2 46.38,85.13 45.74,85.77 45.74,92.9 44.99,93.73 43.9,93.73 42.18,95.45 40.02,95.45 38.71,94.14 38.71,93.06 35.47,89.81 34.74,89.81 34.73,89.83 | R15.2 29.19,87 32.02,89.83 32.66,89.83
N$25
  Bottom 1.27: R22.1 D1.A
N$26  (1 unrouted)
N$27  (via drill 0.61 pad 2.54)
  Top 1.778: v60.99,54 v76.24,54
  Bottom 0.762: 60.97,57.81 57.16,57.81 R16.1 D7.A | J10.1 64.76,69.22
  Bottom 1.27: R14.2 43.88,60.31 45.11,59.08 47.37,59.08 48.64,57.81 60.97,57.81 R27.1
  Bottom 1.778: R27.1 61.02,54.03 v60.99,54 | v76.24,54 80.08,54 R20.1 | 64.81,61.6 64.81,63.52 64.76,69.22 64.75,69.87 60.96,69.85 59.69,71.12 59.69,74.93 60.96,76.2 64.8,76.23 64.22,76.23 J6.1
  Bottom 1.93: R27.1 64.81,61.6
  Bottom 3.81: J1.3 85.85,42.55 85.76,42.57 83.91,45.05 R20.1
N$28  (via drill 2 pad 3.3)
  other vias: 28.86,16.86
N$29  (via drill 0.61 pad 1.93)
  Top 0.254: v19.05,60.33 v29.21,60.33
  Bottom 0.762: IC3.2 9.53,70.48 11.12,68.89 11.12,63.81 14.61,60.33 C11.1 | C11.1 v19.05,60.33 | v29.21,60.33 33.63,60.33 R14.1 | C11.1
N$30
  Bottom 0.762: IC3.5 14.02,65.41 12.87,66.56 12.87,72.83 10.81,74.89 10.81,77.95 J14.1
N$31  (2 unrouted)
N$32  (1 unrouted)
N$33
  Bottom 0.762: R15.1 19.03,80.48 16.8,82.7 8.19,82.7 3.56,78.03 3.56,69.32 4.92,67.96 8.22,67.96 IC3.3
N$34  (via drill 0.61 pad 1.93)
  Top 0.254: v19.03,62.87 v29.19,62.87
  Bottom 0.762: R22.2 v19.03,62.87 | 33.01,65.41 D5.C 33.61,65.44 | v29.19,62.87 29.83,62.87 | R22.2 19.03,62.92 19.06,62.9 15.84,62.9 C11.2 | R22.2 19.03,65.64 16.8,67.87 15.93,67.87 IC3.6
  Bottom 0.813: 29.83,62.87 32.4,65.44 33.61,65.44
N$35  (2 unrouted)
N$36
  Bottom 0.762: R10.1 5.47,75.82 IC3.1
N$38  (via drill 0.61 pad 4)
  other vias: 76.2,49.08
N$40  (1 unrouted)
N$42
  Bottom 0.762: 85.68,67.34 85.13,67.34 T3.3
  Bottom 1.93: R27.2 76.26,57.92 85.68,67.34
  Bottom 2.184: J1.4 91.42,47.59 93.86,50.03 93.86,64.02 90.54,67.34 85.68,67.34
N$43
  Bottom 1.016: R13.2 10.77,86.4 11.79,87.43 15.17,90.8 P3.E
N$44
  Bottom 1.016: P3.A 15.19,95.04 11.7,91.54 8.42,88.25 6.26,88.21 5.56,87.53 R10.2
N$46
  Bottom 0.762: P4.S 6.78,47.02 D9.A
N$47
  Bottom 0: 63.5,47.62 68.58,47.62
N$50
  Bottom 0.762: P3.S J13.2
N$51
  Bottom 0.762: R13.1 8.15,79.9 9.22,80.97 12.78,80.97 13.34,80.41 J14.2
N$52
  Bottom 0.762: IC3.8 15.86,77.95 J14.3
N$54  (1 unrouted)
N$55  (1 unrouted)
REF-7,15V  (4 unrouted)
  Bottom 0.762: D6.A 29.29,71.22
  Bottom 0.813: IC1.3 35.54,46.99 37.45,48.9 40.64,48.9 42.56,50.82 47.75,50.82
  Bottom 1.016: C5.+ 29.22,38.12 31.13,36.21 45.7,36.2 48.24,38.73 48.24,46.99 47.75,47.62 47.75,50.82 47.75,55.1 46.34,56.52 42.1,56.52 38.75,59.87 38.75,67.34 37.48,68.61 R8.1
  Bottom 1.27: R9.2 33.6,70.55 | R9.2 R7.2 35.64,73.76 36.81,74.93 36.81,79.38 35.54,80.64 R11.2 R12.1 | 29.29,71.22 R9.2 | R3.2 R2.2 IC1.3
V+  (via drill 0.61 pad 2.18, 0.61 pad 4)  (1 unrouted)
  Top 0.813: v79.38,67.31 v67.31,67.31
  Top 1.778: v60.99,40.66 v76.24,40.66
  Bottom 0.762: T3.2 80.05,70.52 C19.2 | C18.2 55.09,21.52 60.51,21.52 C10.+
  Bottom 0.813: J10.2 66.67,72.39 67.31,71.75 v67.31,67.31
  Bottom 1.016: v79.38,67.31 79.38,69.85 C19.2
  Bottom 1.676: 53.32,47.61 53.32,43.88 59.72,37.48 | 53.32,47.61 D7.C | 53.32,47.61 v53.34,52.07
  Bottom 1.778: C19.2 83.89,70.49 | J1.2 91.43,37.48 95.93,37.48 97.84,39.39 97.84,65.44 92.75,70.52 T3.2
  Bottom 3.4: J1.2 J1.1
  Bottom 3.81: J1.2 79.42,37.47 v76.24,40.66 | v60.99,40.66 59.72,37.48 59.71,22.92 C10.+ 60.59,22.94 59.96,22.32 38.95,22.32 B1.+1 | 59.35,36.76 57.92,37.17 44.2,23.5 57.25,23.8 57.25,34.04 57.2,34.09 57.05,34.09 48.51,25.55 52.57,25.55 55.6,28.59
(copper drawn outside any net)
  shapes: Bottom circle x4

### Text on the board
Top: Rectifier | Bottom
Bottom: 24-02-2012 | Michael D. | (+) | ~ | ~ | ~ | (-) | Ver.MOD-5.4.1 | ~ | 100x100mm
Dimension: 24-02-2012
tPlace: ON | Stby | (3) | (2) | (1) | (0)V | ON | Stby | (-)12V | P3 | Switch | (+)12V | Offset Strom | P2 1k | Pin5 | Pin1 | Pin8 | Volt | Amp. | Pin1 | U(+) | IN | U(+) | OUT | Messeingang | P1 50k | (-)12V | (+)12V
bOrigins: Ver.MOD-5.4.1 | 100x100mm | optional | Vorregler
tNames: B | E | C1 | ~30V | C2 | ~30V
